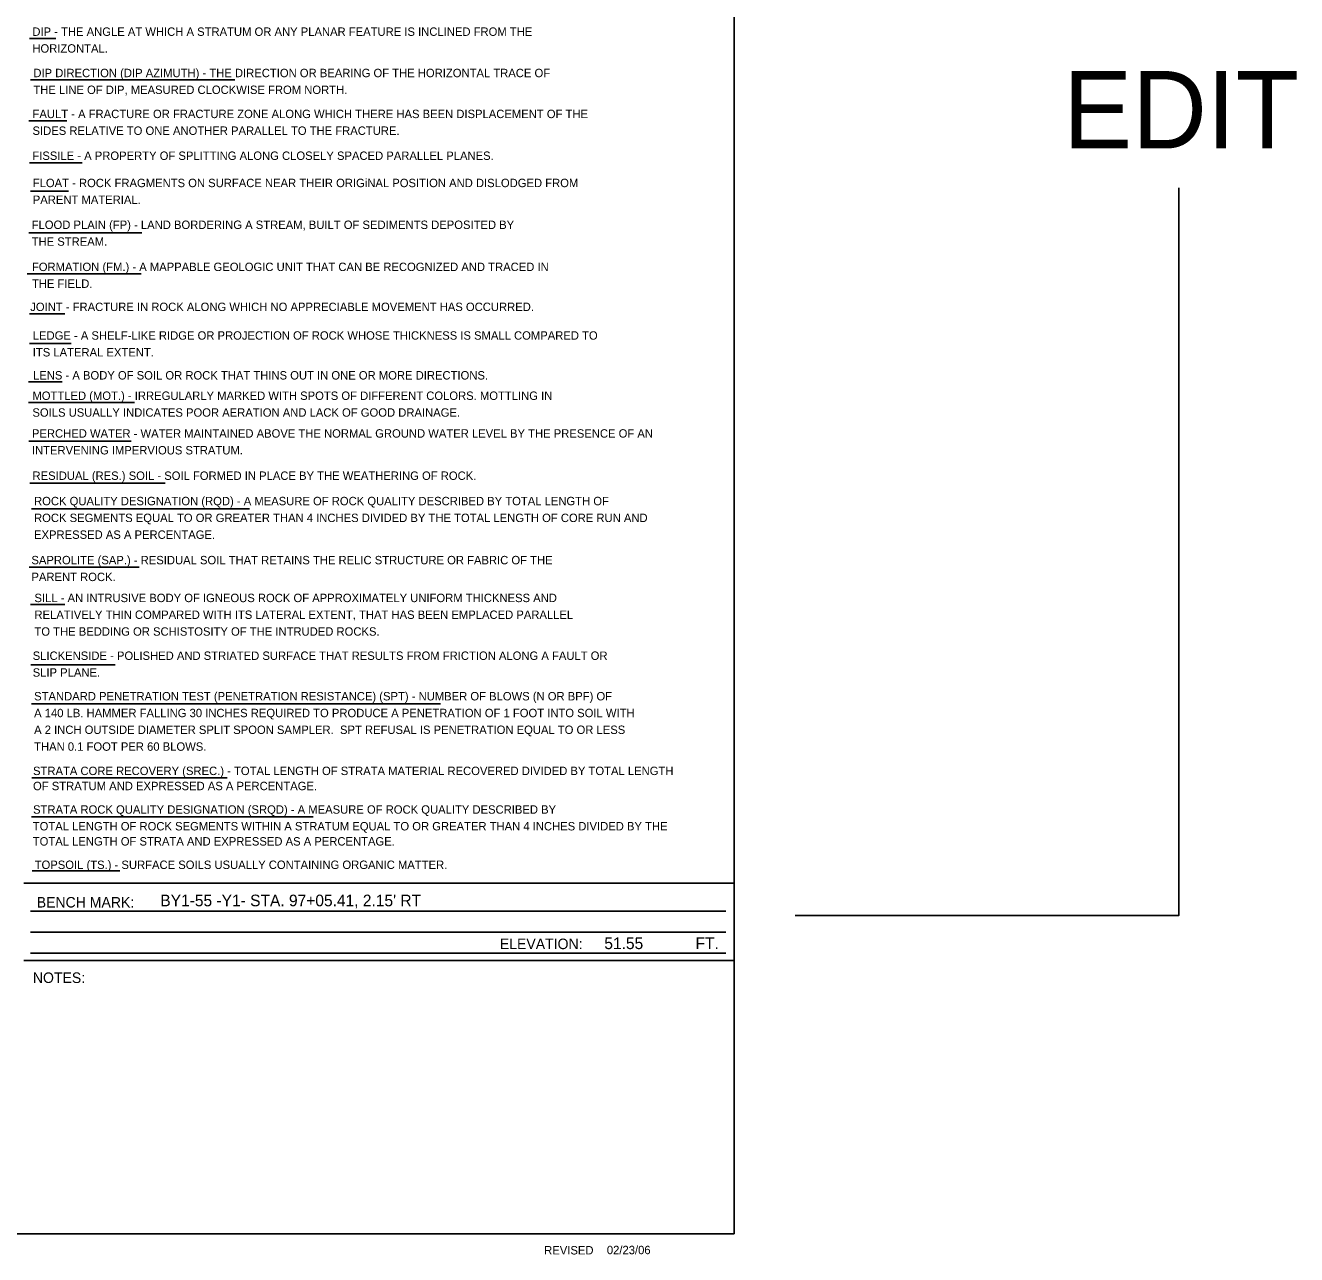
# Model space of a CAD drawing. Extents: x 278710 to 279187, y 171464 to 171625.
# Drawn here: x 279121.4 to 279187.1, y 171484.7 to 171548.2 of the extents above; entities that cross this region are included whole.
import ezdxf

# ---------------------------------------------------------------- set-up
doc = ezdxf.new("R2010")
doc.units = 0
doc.layers.add('Prop Strc Sect_ Misc - User Comment (Tx - small)', color=7, linetype='Continuous')

msp = doc.modelspace()

# ---------------------------------------------------------------- linework, layer by layer
at = {"layer": 'Prop Strc Sect_ Misc - User Comment (Tx - small)'}
for p, q in [((279158.027, 171581.203), (279158.027, 171485.806)), ((279158.027, 171566.918), (279158.027, 171485.806)), ((279121.64, 171547.54), (279122.994, 171547.54)), ((279121.679, 171545.41), (279132.238, 171545.41)), ((279121.601, 171543.285), (279123.562, 171543.285)), ((279121.64, 171541.116), (279124.351, 171541.116)), ((279121.684, 171539.667), (279123.644, 171539.667)), ((279121.592, 171537.507), (279127.425, 171537.507)), ((279121.51, 171535.398), (279121.549, 171535.398)), ((279121.549, 171535.398), (279127.397, 171535.398)), ((279121.64, 171533.32), (279123.462, 171533.32)), ((279121.636, 171531.793), (279123.783, 171531.793)), ((279121.588, 171529.807), (279123.319, 171529.807)), ((279121.584, 171528.739), (279127.05, 171528.739)), ((279121.601, 171526.74), (279126.885, 171526.74)), ((279121.649, 171524.584), (279128.643, 171524.584)), ((279121.727, 171523.252), (279132.988, 171523.252)), ((279121.614, 171520.241), (279127.295, 171520.241)), ((279121.684, 171518.307), (279123.458, 171518.307)), ((279121.705, 171515.205), (279126.052, 171515.205)), ((279121.727, 171513.192), (279142.853, 171513.192)), ((279121.749, 171509.357), (279131.843, 171509.357)), ((279121.74, 171507.344), (279136.277, 171507.344)), ((279121.762, 171504.551), (279126.304, 171504.551)), ((279121.332, 171503.922), (279158.027, 171503.922)), ((279121.688, 171502.482), (279157.589, 171502.482)), ((279121.688, 171501.397), (279157.589, 171501.397)), ((279121.332, 171499.931), (279158.027, 171499.931)), ((279121.688, 171500.313), (279157.589, 171500.313)), ((279005.33, 171485.806), (279158.027, 171485.806))]:
    msp.add_line(p, q, dxfattribs=at)
msp.add_lwpolyline([(279180.983, 171539.824), (279180.983, 171502.252), (279161.167, 171502.252)], dxfattribs=at)

# ---------------------------------------------------------------- texts
for s, height, p in [('DIP - THE ANGLE AT WHICH A STRATUM OR ANY PLANAR FEATURE IS INCLINED FROM THE', 0.43381, (279121.779, 171547.679)), ('HORIZONTAL.', 0.43381, (279121.779, 171546.812)), ('DIP DIRECTION (DIP AZIMUTH) - THE DIRECTION OR BEARING OF THE HORIZONTAL TRACE OF ', 0.43381, (279121.831, 171545.545)), ('EDIT', 4, (279175.002, 171541.867)), ('THE LINE OF DIP, MEASURED CLOCKWISE FROM NORTH.', 0.43381, (279121.831, 171544.677)), ('FAULT - A FRACTURE OR FRACTURE ZONE ALONG WHICH THERE HAS BEEN DISPLACEMENT OF THE', 0.43381, (279121.788, 171543.432)), ('SIDES RELATIVE TO ONE ANOTHER PARALLEL TO THE FRACTURE.', 0.43381, (279121.788, 171542.565)), ('FISSILE - A PROPERTY OF SPLITTING ALONG CLOSELY SPACED PARALLEL PLANES.', 0.43381, (279121.779, 171541.272)), ('FLOAT - ROCK FRAGMENTS ON SURFACE NEAR THEIR ORIGiNAL POSITION AND DISLODGED FROM ', 0.43381, (279121.801, 171539.866)), ('PARENT MATERIAL.', 0.43381, (279121.801, 171538.999)), ('FLOOD PLAIN (FP) - LAND BORDERING A STREAM, BUILT OF SEDIMENTS DEPOSITED BY', 0.43381, (279121.744, 171537.706)), ('THE STREAM.', 0.43381, (279121.744, 171536.839)), ('FORMATION (FM.) - A MAPPABLE GEOLOGIC UNIT THAT CAN BE RECOGNIZED AND TRACED IN', 0.43381, (279121.757, 171535.533)), ('THE FIELD.', 0.4338, (279121.757, 171534.665)), ('JOINT - FRACTURE IN ROCK ALONG WHICH NO APPRECIABLE MOVEMENT HAS OCCURRED.', 0.43381, (279121.67, 171533.468)), ('LEDGE - A SHELF-LIKE RIDGE OR PROJECTION OF ROCK WHOSE THICKNESS IS SMALL COMPARED TO ', 0.43381, (279121.801, 171531.989)), ('ITS LATERAL EXTENT.', 0.43381, (279121.801, 171531.121)), ('LENS - A BODY OF SOIL OR ROCK THAT THINS OUT IN ONE OR MORE DIRECTIONS.', 0.43381, (279121.814, 171529.932)), ('MOTTLED (MOT.) - IRREGULARLY MARKED WITH SPOTS OF DIFFERENT COLORS. MOTTLING IN ', 0.43381, (279121.783, 171528.878)), ('SOILS USUALLY INDICATES POOR AERATION AND LACK OF GOOD DRAINAGE.', 0.43381, (279121.783, 171528.011)), ('PERCHED WATER - WATER MAINTAINED ABOVE THE NORMAL GROUND WATER LEVEL BY THE PRESENCE OF AN ', 0.43381, (279121.757, 171526.93)), ('INTERVENING IMPERVIOUS STRATUM.', 0.43381, (279121.757, 171526.063)), ('RESIDUAL (RES.) SOIL - SOIL FORMED IN PLACE BY THE WEATHERING OF ROCK.', 0.43381, (279121.788, 171524.748)), ('ROCK QUALITY DESIGNATION (RQD) - A MEASURE OF ROCK QUALITY DESCRIBED BY TOTAL LENGTH OF ', 0.43381, (279121.866, 171523.438)), ('ROCK SEGMENTS EQUAL TO OR GREATER THAN 4 INCHES DIVIDED BY THE TOTAL LENGTH OF CORE RUN AND ', 0.43381, (279121.866, 171522.571)), ('EXPRESSED AS A PERCENTAGE.', 0.43381, (279121.866, 171521.704)), ('SAPROLITE (SAP.) - RESIDUAL SOIL THAT RETAINS THE RELIC STRUCTURE OR FABRIC OF THE ', 0.43381, (279121.731, 171520.389)), ('PARENT ROCK.', 0.43381, (279121.731, 171519.522)), ('SILL - AN INTRUSIVE BODY OF IGNEOUS ROCK OF APPROXIMATELY UNIFORM THICKNESS AND', 0.43381, (279121.887, 171518.436)), ('RELATIVELY THIN COMPARED WITH ITS LATERAL EXTENT, THAT HAS BEEN EMPLACED PARALLEL', 0.43381, (279121.887, 171517.569)), ('TO THE BEDDING OR SCHISTOSITY OF THE INTRUDED ROCKS.', 0.43381, (279121.887, 171516.702)), ('SLICKENSIDE - POLISHED AND STRIATED SURFACE THAT RESULTS FROM FRICTION ALONG A FAULT OR ', 0.43381, (279121.796, 171515.452)), ('SLIP PLANE.', 0.43381, (279121.796, 171514.585)), ('STANDARD PENETRATION TEST (PENETRATION RESISTANCE) (SPT) - NUMBER OF BLOWS (N OR BPF) OF ', 0.43381, (279121.87, 171513.36)), ('A 140 LB. HAMMER FALLING 30 INCHES REQUIRED TO PRODUCE A PENETRATION OF 1 FOOT INTO SOIL WITH ', 0.43381, (279121.87, 171512.494)), ('A 2 INCH OUTSIDE DIAMETER SPLIT SPOON SAMPLER.  SPT REFUSAL IS PENETRATION EQUAL TO OR LESS', 0.43381, (279121.87, 171511.627)), ('THAN 0.1 FOOT PER 60 BLOWS.', 0.43381, (279121.87, 171510.76)), ('STRATA CORE RECOVERY (SREC.) - TOTAL LENGTH OF STRATA MATERIAL RECOVERED DIVIDED BY TOTAL LENGTH', 0.43381, (279121.814, 171509.505)), ('OF STRATUM AND EXPRESSED AS A PERCENTAGE.', 0.43381, (279121.814, 171508.724)), ('STRATA ROCK QUALITY DESIGNATION (SRQD) - A MEASURE OF ROCK QUALITY DESCRIBED BY', 0.43381, (279121.814, 171507.509)), ('TOTAL LENGTH OF ROCK SEGMENTS WITHIN A STRATUM EQUAL TO OR GREATER THAN 4 INCHES DIVIDED BY THE', 0.43381, (279121.801, 171506.646)), ('TOTAL LENGTH OF STRATA AND EXPRESSED AS A PERCENTAGE.', 0.43381, (279121.801, 171505.865)), ('TOPSOIL (TS.) - SURFACE SOILS USUALLY CONTAINING ORGANIC MATTER.', 0.43381, (279121.9, 171504.655)), ('BENCH MARK:', 0.54224, (279122.005, 171502.664)), ("BY1-55 -Y1- STA. 97+05.41, 2.15' RT", 0.6, (279128.387, 171502.729)), ('51.55', 0.6, (279151.316, 171500.517)), ('FT.', 0.6, (279156.026, 171500.517)), ('ELEVATION:', 0.5422, (279145.92, 171500.516)), ('NOTES:', 0.5422, (279121.805, 171498.768)), ('REVISED ', 0.4338, (279148.21, 171484.748)), ('02/23/06', 0.4338, (279151.447, 171484.761))]:
    msp.add_text(s, height=height, dxfattribs=at).set_placement(p)

doc.saveas('drawing.dxf')
